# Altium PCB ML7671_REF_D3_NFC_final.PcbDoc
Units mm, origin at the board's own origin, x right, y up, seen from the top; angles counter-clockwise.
Board outline 64 x 8.2 mm, 4 copper layers (Top Layer, Inner Layer 1, Inner Layer 2, Bottom Layer), stack 0.195 mm thick; 63 components, 45 nets, 175 pads, 328 vias.
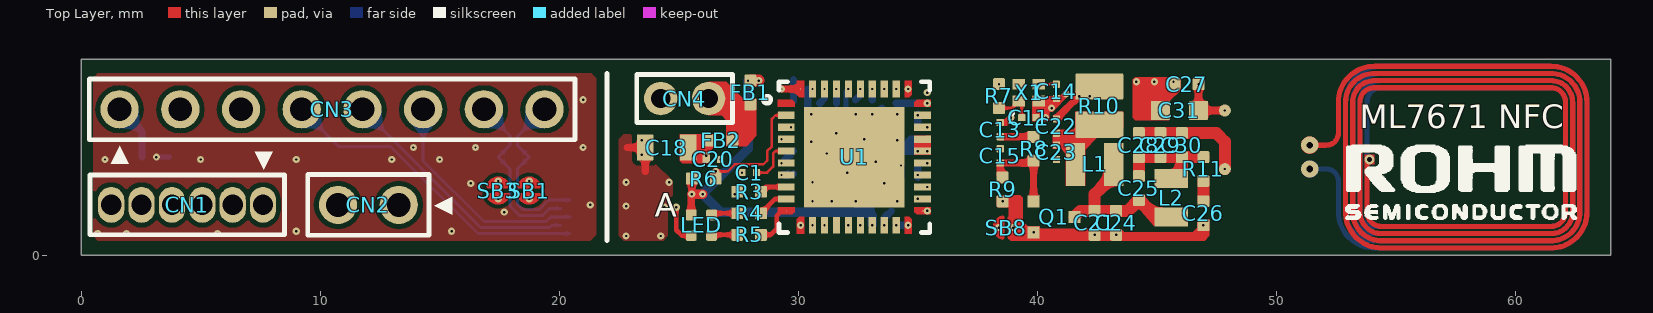
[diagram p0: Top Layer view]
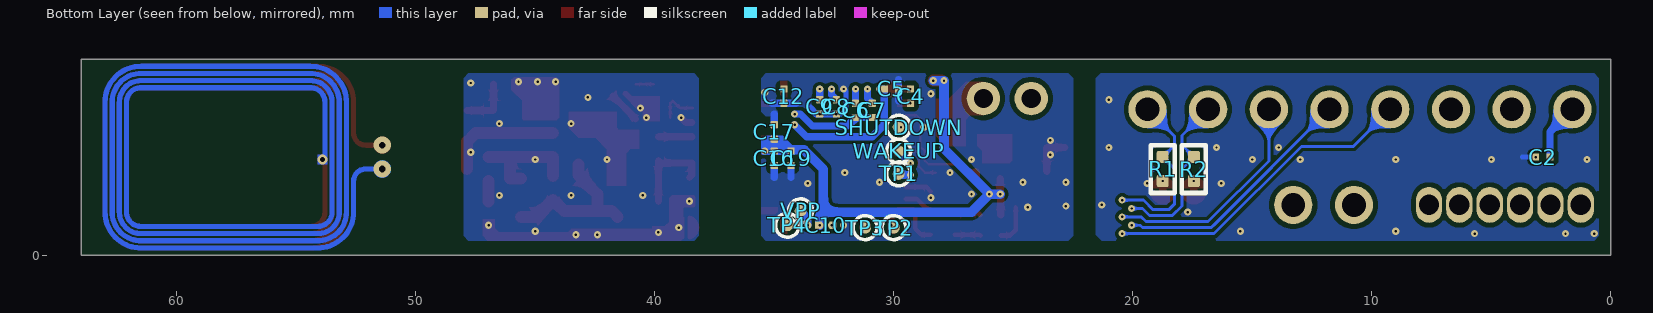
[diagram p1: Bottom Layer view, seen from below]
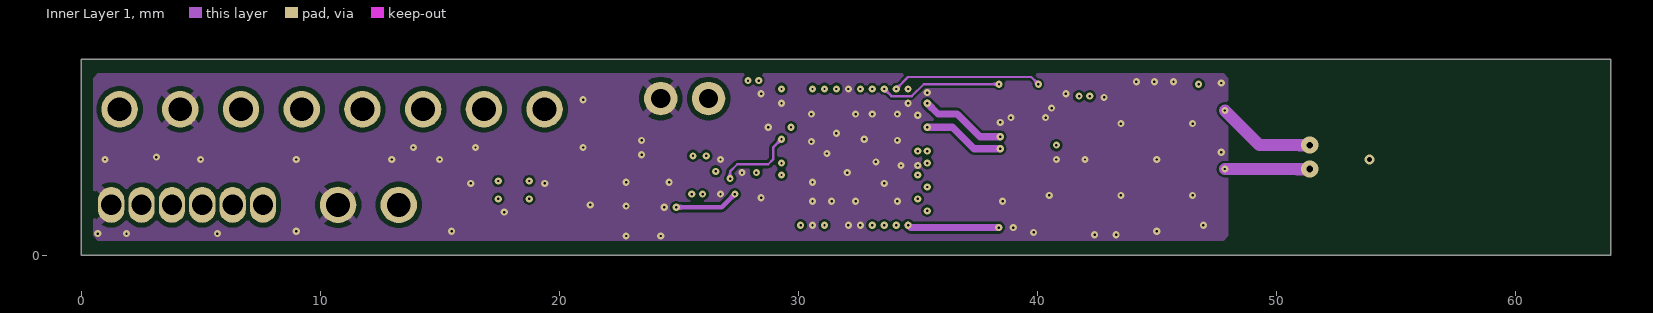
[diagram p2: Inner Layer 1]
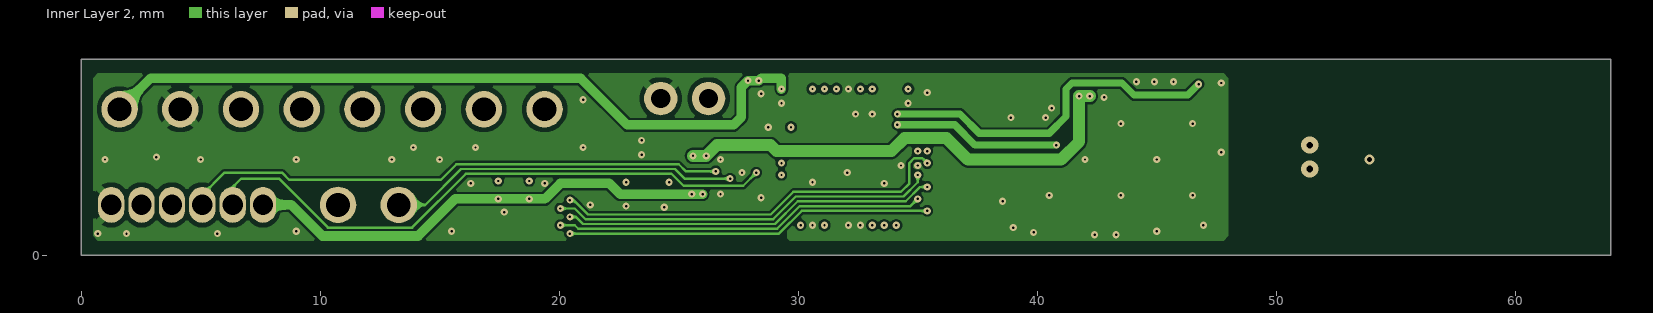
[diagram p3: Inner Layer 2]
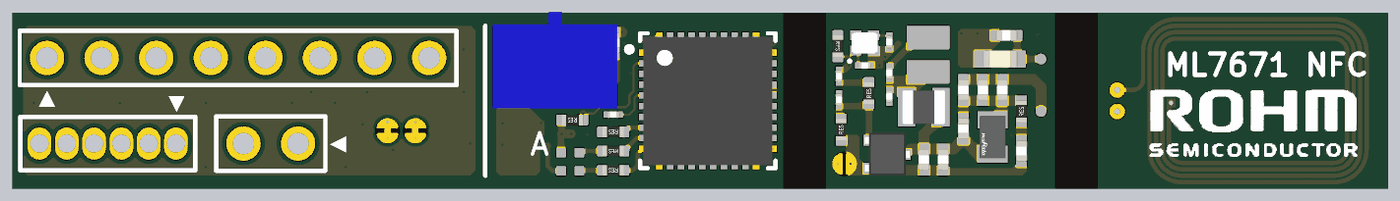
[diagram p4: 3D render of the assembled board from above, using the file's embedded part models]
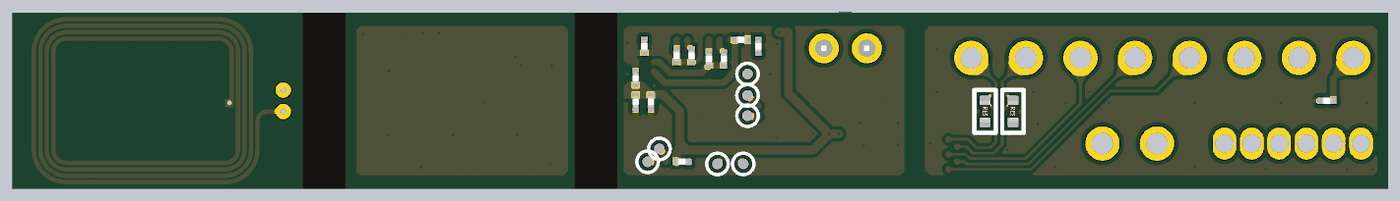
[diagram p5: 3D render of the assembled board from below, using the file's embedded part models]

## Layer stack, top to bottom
Top Solder: solder mask 0.02, Solder Resist, Dk 3.5
Top Layer: signal copper 0.035
Dielectric 1: prepreg 0.005, Composite dielectric, Dk 4.1
Dielectric 2: prepreg 0.025, Composite dielectric, Dk 4.1
Inner Layer 1: signal copper 0.02
Dielectric 3: core 0.025, R-1776KR, Dk 4.8
Inner Layer 2: signal copper 0.02
Dielectric 4: prepreg 0.025, Composite dielectric, Dk 4.1
Dielectric 5: prepreg 0.005, Composite dielectric, Dk 4.1
Bottom Layer: signal copper 0.035
Bottom Solder: solder mask 0.02, Solder Resist, Dk 3.5

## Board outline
0,0 0,8.2 64,8.2 64,0

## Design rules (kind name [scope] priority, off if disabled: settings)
BoardOutlineClearance [All] p1: gap=0.5 ignorepadtopadclearanceinfootprint=FALSE
Clearance Clearance_1 [IsKeepOut] p1: gap=0 ignorepadtopadclearanceinfootprint=TRUE
Clearance Clearance_l2 [OnLayer('Inner Layer 1')] p2: gap=0.1 ignorepadtopadclearanceinfootprint=TRUE except(0: Arc-Text Track-Text SMDPad-Text THPad-Text Via-Text Fill-Text Poly-Text Region-Text; 0.15: Arc-SMDPad Track-SMDPad SMDPad-Via THPad-Via; 0.2: Arc-THPad Arc-Hole Track-THPad Track-Hole SMDPad-SMDPad SMDPad-THPad SMDPad-Fill SMDPad-Poly SMDPad-Region SMDPad-Hole THPad-THPad THPad-Fill THPad-Poly THPad-Region THPad-Hole Via-Hole Fill-Hole Poly-Hole Region-Region Region-Hole; 0.3: Fill-Fill Fill-Poly Fill-Region)
Clearance Clearance_l3 [OnLayer('Inner Layer 2')] p3: gap=0.1 ignorepadtopadclearanceinfootprint=TRUE except(0: Arc-Text Track-Text SMDPad-Text THPad-Text Via-Text Fill-Text Poly-Text Region-Text; 0.15: Arc-SMDPad Track-SMDPad SMDPad-Via THPad-Via; 0.2: Arc-THPad Arc-Hole Track-THPad Track-Hole SMDPad-SMDPad SMDPad-THPad SMDPad-Fill SMDPad-Poly SMDPad-Region SMDPad-Hole THPad-THPad THPad-Fill THPad-Poly THPad-Region THPad-Hole Via-Hole Fill-Hole Poly-Hole Region-Region Region-Hole; 0.3: Fill-Fill Fill-Poly Fill-Region Poly-Poly)
Clearance Clearance_bottom [OnLayer('Bottom Layer')] p4: gap=0.2 ignorepadtopadclearanceinfootprint=TRUE except(0.1: Text-Text Text-Hole; 0.13: Arc-Arc Arc-Track Arc-Via Track-Track Track-Via; 0.15: Arc-SMDPad Arc-Fill Arc-Poly Arc-Region Track-SMDPad Track-Fill Track-Poly Track-Region SMDPad-Via THPad-Via Via-Via Via-Fill Via-Poly Via-Region Poly-Region; 0.3: Fill-Fill Fill-Poly Fill-Region Poly-Poly)
Clearance Clearance_top [OnLayer('Top Layer')] p5: gap=0.2 ignorepadtopadclearanceinfootprint=TRUE except(0.1: Text-Text Text-Hole; 0.13: Arc-Arc Arc-Track Arc-Via Track-Track Track-Via; 0.15: Arc-SMDPad Arc-Fill Arc-Poly Arc-Region Track-SMDPad Track-Fill Track-Poly Track-Region SMDPad-Via Via-Via Via-Fill Via-Poly Via-Region Poly-Region; 0.3: Fill-Fill Fill-Poly Fill-Region Poly-Poly)
HoleSize [All] p1: absolutevalues=TRUE maxlimit=4 minlimit=0.2 maxpercent=80.000 minpercent=20.000
MinimumSolderMaskSliver [All] p1: minsoldermaskwidth=0.15
PolygonConnect PolygonConnect_top [OnLayer('Top Layer')] p1: thpad.connectstyle=NoConnect thpad.reliefconductorwidth=0.3 thpad.reliefentries=4 thpad.polygonreliefangle="90 Angle" thpad.airgapwidth=0.2 smdpad.connectstyle=NoConnect smdpad.reliefconductorwidth=0.254 smdpad.reliefentries=4 smdpad.polygonreliefangle="90 Angle" smdpad.airgapwidth=0.2 via.connectstyle=Direct via.reliefconductorwidth=0.254 via.reliefentries=4 via.polygonreliefangle="90 Angle" via.airgapwidth=0.254
PolygonConnect PolygonConnect_bottom [OnLayer('Bottom Layer')] p2: thpad.connectstyle=NoConnect thpad.reliefconductorwidth=0.3 thpad.reliefentries=4 thpad.polygonreliefangle="90 Angle" thpad.airgapwidth=0.2 smdpad.connectstyle=NoConnect smdpad.reliefconductorwidth=0.254 smdpad.reliefentries=4 smdpad.polygonreliefangle="90 Angle" smdpad.airgapwidth=0.2 via.connectstyle=Direct via.reliefconductorwidth=0.254 via.reliefentries=4 via.polygonreliefangle="90 Angle" via.airgapwidth=0.254
PolygonConnect [All] p3: thpad.connectstyle=Relief thpad.reliefconductorwidth=0.3 thpad.reliefentries=4 thpad.polygonreliefangle="90 Angle" thpad.airgapwidth=0.2 thpad.conductorbypadedge=TRUE thpad.mindistance=0.381 thpad.enablemindistance=FALSE smdpad.connectstyle=NoConnect smdpad.reliefconductorwidth=0.254 smdpad.reliefentries=4 smdpad.polygonreliefangle="90 Angle" smdpad.airgapwidth=0.2 via.connectstyle=Direct via.reliefconductorwidth=0.254 via.reliefentries=4 via.polygonreliefangle="90 Angle" via.airgapwidth=0.254
RoutingVias [All] p1: holewidth=0.6 width=0.3 viastyle="Through Hole" minholewidth=0.5 minwidth=0.2 maxholewidth=1.4 maxwidth=1
SilkToSilkClearance [All] p1: silktosilkclearance=0.1
SilkToSolderMaskClearance [IsPad] p1: minsilkscreentomaskgap=0.1 clearancetoexposedcopper=TRUE
SolderMaskExpansion [All] p1: expansion=0.05 istentingtop=FALSE
SupplyNets "Schematic Supply Nets_6" [InNet('VDD_IO')] p1: voltage=0.000
SupplyNets "Schematic Supply Nets_2" [InNet('GND')] p2: voltage=0.000
Width [All] p1: maxlimit=3 minlimit=0.1 preferedwidth=0.12 midlayer1_prefwidth=0.1 midlayer2_prefwidth=0.1 minimp=50.000000 maximp=50.000000 favimp=50.000000
26 further rules are at their usual default settings.

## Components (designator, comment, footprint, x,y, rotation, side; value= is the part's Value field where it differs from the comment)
C1 "Cap" 0603-1_00 27.95,3.45 r180 top value=N.M.
C2 "Cap" 0603-1_00 2.85,4.1 r0 bottom value=0.1uF
C4 "Cap" 0603-1_00 29.3,6.65 r270 bottom value=2.2uF
C5 "Cap" 0603-1_00 30.1,6.95 r180 bottom value=N.M.
C6 "Cap" 0603-1_00 31.6,6.05 r270 bottom value=560pF
C7 "Cap" 0603-1_00 30.9,6.05 r270 bottom value=560pF
C8 "Cap" 0603-1_00 32.4,6.2 r90 bottom value=0.47uF
C9 "Cap" 0603-1_00 33.1,6.2 r90 bottom value=2.2uF
C10 "Cap" 0603-1_00 32.85,1.25 r180 bottom value=0.1uF
C11 "Cap" 0603-1_00 39.65,5.75 r180 top value=10pF
C12 "Cap" 0603-1_00 34.6,6.65 r270 bottom value=0.47uF
C13 "Cap" 0603-1_00 38.45,5.25 r90 top value=1nF
C14 "Cap" 0603-1_00 40.8,6.85 r90 top value=10pF
C15 "Cap" 0603-1_00 38.45,4.15 r270 top value=1nF
C16 "Cap" 0603-1_00 35,4.05 r270 bottom value=47pF
C17 "Cap" 0603-1_00 35,5.15 r90 bottom value=47pF
C18 "Cap" GCM21_2125_00 24.5,4.5 r180 top value=47uF
C19 "Cap" 0603-1_00 34.3,4.05 r270 bottom value=2.2uF
C20 "Cap" 0603-1_00 26.45,4 r0 top value=2.2uF
C21 "Cap" CC1005_02 42.4,1.35 r270 top value=120pF
C22 "Cap" 0603-1_00 40.8,5.4 r270 top value=100pF
C23 "Cap" 0603-1_00 40.8,4.3 r270 top value=100pF
C24 "Cap" CC1005_02 43.3,1.35 r270 top value=N.M.
C25 "N.M." CC1005_02 44.25,2.8 r90 top
C26 "N.M." CC1005_02 46.95,1.75 r270 top
C27 "Cap" CC1005_02 46.25,7.15 r0 top value=390pF
C28 "Cap" CC1005_02 44.25,4.6 r90 top value=120pF
C29 "Cap" CC1005_02 45.15,4.6 r90 top value=12pF
C30 "Cap" CC1005_02 46.05,4.6 r90 top value=N.M.
C31 "Cap" CC1608_00 45.95,6.05 r0 top value=2.2nF
CN1 "MHDR1X6" CN6_XB-1-5 7.61,2.1 r180 top value="6-Pin Header"
CN2 "Header 2" JP2-2.54_01 12.02,2.1 r180 top value="2-Pin Header"
CN3 "Header 8" JP8-2.54_01 10.5,6.1 r0 top value="8-Pin Header"
CN4 "Header 2" JP2-2.0_C0.8 25.25,6.55 r180 top locked value="2-Pin Header"
FB1 "BLM15AG" CC1005_02 28,6.8 r270 top value=-
FB2 "BLM15AG" CC1005_02 26.75,4.8 r0 top value=-
L1 "DFE2016CKA-1R0M" L_2_2016_t065 42.4,3.8 r180 top value=4.7uH
L2 "DFE21CCNR24MELL1" L_2_2012_t08 45.6,2.4 r270 top value=240nH
LED "SMLP34RGBN1W3" SMLP34RGB_00 25.95,1.25 r90 top value=-
Q1 "RSF014N03TL" MMP_3_2120_TUMT_GSD 40.7,1.6 r0 top value=-
R1 "2.2kΩ" RR1005_02 18.75,3.6 r270 bottom
R2 "2.2kΩ" RR1005_02 17.45,3.6 r270 bottom
R3 "1.8kΩ" RR1005_02 27.95,2.65 r180 top
R4 "1.8kΩ" RR1005_02 27.95,1.75 r180 top
R5 "1.8kΩ" RR1005_02 27.95,0.85 r180 top
R6 "2.2kΩ" RR1005_02 26.05,3.2 r180 top
R7 "0Ω" RR1005_02 38.4,6.65 r270 top
R8 "51Ω" RR1005_02 39.85,4.45 r90 top
R9 "510Ω" RR1005_02 38.55,2.75 r90 top
R10 "220mΩ" LTR10_00 42.6,6.25 r270 top
R11 "N.M." RR1005_02 46.95,3.6 r90 top
SB1 "Solderbridge Shorted" SOLDERBRIDGE_SHORTED_POWER 18.75,2.7 r90 top
SB3 "Solderbridge Shorted" SOLDERBRIDGE_SHORTED_POWER 17.45,2.7 r90 top
SB8 "Solderbridge" SOLDERBRIDGE 38.7,1.15 r180 top
SHUTDOWN "" TP_PAD0.5_01 29.8,5.35 r90 bottom value="Small Pad"
TP1 "" TP_PAD0.5_01 29.8,3.4 r180 bottom value="Small Pad"
TP2 "" TP_PAD0.5_01 30,1.15 r90 bottom value="Small Pad"
TP3 "" TP_PAD0.5_01 31.2,1.15 r90 bottom value="Small Pad"
TP4 "" TP_PAD0.5_01 34.45,1.25 r90 bottom value="Small Pad"
U1 "-" QFN50P600X600X80_41N_ROHM 32.35,4.1 r0 top
VPP "" TP_PAD0.5_01 33.9,1.85 r90 bottom value="Small Pad"
WAKEUP "" TP_PAD0.5_01 29.8,4.35 r90 bottom value="Small Pad"
X1 "CX1210SB27120B0FLKC2" X_4_1210_0.52x0.45 39.65,6.8 r0 top value=-

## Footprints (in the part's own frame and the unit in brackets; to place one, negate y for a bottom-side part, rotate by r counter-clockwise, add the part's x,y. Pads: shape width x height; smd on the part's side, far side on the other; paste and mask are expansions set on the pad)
0603-1_00 [mm]
  rrect17% 0.3x0.3 smd: 1(-0.3,0) 2(0.3,0)
  body extent -0.3,-0.16 0.3,0.16, height 0.32
CC1005_02 [mm]
  rrect22% 0.5x0.5 smd: 1(-0.5,0) 2(0.5,0)
  body extent -0.5,-0.26 0.5,0.26, height 0.52
CC1608_00 [mm]
  rrect12% 0.8x0.8 smd: 1(-0.8,0) 2(0.8,0)
  body extent -0.8,-0.41 0.8,0.41, height 0.82
CN6_XB-1-5 [mm] "XB-1-5-6P プリント板ニ段重ね用コンスルー"
  oval 1.1x1.5 hole 0.85 mask-2539.97: 1(0,0) 2(1.27,0) 3(2.54,0) 4(3.81,0) 5(5.08,0) 6(6.35,0)
  silkscreen extent -0.9,-1.25 7.24,1.25
GCM21_2125_00 [mm]
  rrect14% 0.7x1.1 smd: 1(-0.9,0) 2(0.9,0)
  body extent -1,-0.63 1,0.64, height 0.87
JP2-2.0_C0.8 [mm]
  round 1.4 hole 0.8: 1(-1,0) 2(1,0)
  silkscreen extent -2,-1 2,1, body extent -2.9,-1.7 2.9,2.8, height 8.13
JP2-2.54_01 [mm]
  round 1.6 / inner round 1.524 / far side round 1.6 hole 1: 1(-1.27,0) 2(1.27,0)
  silkscreen extent -2.54,-1.27 2.54,1.27
JP8-2.54_01 [mm]
  round 1.6 / inner round 1.524 / far side round 1.6 hole 1: 1(-8.89,0) 2(-6.35,0) 3(-3.81,0) 4(-1.27,0) 5(1.27,0) 6(3.81,0) 7(6.35,0) 8(8.89,0)
  silkscreen extent -10.16,-1.27 10.16,1.27
L_2_2012_t08 [mm] "default"
  rect 0.8x1.4 smd paste+0: 1(-0.8,0) 2(0.8,0)
  body extent -1,-0.6 1,0.6, height 0.8
L_2_2016_t065 [mm] "default"
  rect 0.8x1.8 smd paste+0: 1(-0.8,0) 2(0.8,0)
  body extent -1,-0.8 1,0.8, height 0.65
LTR10_00 [mm]
  rrect9% 1.1x2 smd: 1(-0.8,0) 2(0.8,0)
  body extent -0.6,-1 0.6,1, height 0.55
MMP_3_2120_TUMT_GSD [mm] "default"
  rect 0.5x0.5 smd paste+0 mask+0.05: D(0.85,0) G(-0.85,0.65) S(-0.85,-0.65)
  body extent -1.05,-1 1.05,1, height 0.85
QFN50P600X600X80_41N_ROHM [mm] "QFN, 40-Leads, Body 6.00x6.00mm, Pitch 0.50mm, Thermal Pad 4.20x4.20mm"
  round 0.025 smd mask+0: 1(-2.85,2.25) 10(-2.85,-2.25) 11(-2.25,-2.85) 20(2.25,-2.85) 21(2.85,-2.25) 30(2.85,2.25) 31(2.25,2.85) 40(-2.25,2.85)
  rect 0.7x0.3 smd mask+0.05: 2(-2.85,1.75) 3(-2.85,1.25) 4(-2.85,0.75) 5(-2.85,0.25) 6(-2.85,-0.25) 7(-2.85,-0.75) 8(-2.85,-1.25) 9(-2.85,-1.75) 22(2.85,-1.75) 23(2.85,-1.25) 24(2.85,-0.75) 25(2.85,-0.25) 26(2.85,0.25) 27(2.85,0.75) 28(2.85,1.25) 29(2.85,1.75)
  rect 0.3x0.7 smd mask+0.05: 12(-1.75,-2.85) 13(-1.25,-2.85) 14(-0.75,-2.85) 15(-0.25,-2.85) 16(0.25,-2.85) 17(0.75,-2.85) 18(1.25,-2.85) 19(1.75,-2.85) 32(1.75,2.85) 33(1.25,2.85) 34(0.75,2.85) 35(0.25,2.85) 36(-0.25,2.85) 37(-0.75,2.85) 38(-1.25,2.85) 39(-1.75,2.85)
  rect 4.2x4.2 smd mask+0.05: 41(0,0)
  Top Layer region: -2.5,-2.3 -2.6,-2.4 -3.2,-2.4 -3.2,-2.1 -2.5,-2.1
  Top Layer region: 2.3,2.5 2.4,2.6 2.4,3.2 2.1,3.2 2.1,2.5
  Top Layer region: 2.5,2.3 2.6,2.4 3.2,2.4 3.2,2.1 2.5,2.1
  Top Layer region: 2.5,-2.3 2.6,-2.4 3.2,-2.4 3.2,-2.1 2.5,-2.1
  Top Layer region: 2.3,-2.5 2.4,-2.6 2.4,-3.2 2.1,-3.2 2.1,-2.5
  Top Layer region: -2.3,-2.5 -2.4,-2.6 -2.4,-3.2 -2.1,-3.2 -2.1,-2.5
  Top Layer region: -2.3,2.5 -2.4,2.6 -2.4,3.2 -2.1,3.2 -2.1,2.5
  Top Layer region: -2.5,2.3 -2.6,2.4 -3.2,2.4 -3.2,2.1 -2.5,2.1
  silkscreen extent -3.77,-3.15 3.15,3.15, body extent -3,-3 3,3, height 0.8
RR1005_02 [mil]
  rrect22% 19.68x19.68 smd: 1(-19.69,0) 2(19.69,0)
  silkscreen extent -39,-20 39,20, body extent -20,-10 20,10, height 14
SMLP34RGB_00 [mm]
  rrect22% 0.45x0.45 smd: 1(0.425,0.425) 2(0.425,-0.425) 3(-0.425,-0.425) 4(-0.425,0.425)
  body extent -0.5,-0.5 0.5,0.5, height 0.2
SOLDERBRIDGE [mm]
  round 0.2 smd paste-10: 1(-0.312,0) 2(0.312,0)
  Top Layer region: -0.077,-0.432 -0.152,-0.505 -0.271,-0.467 -0.335,-0.424 -0.409,-0.351 -0.462,-0.292 -0.521,-0.193 -0.549,-0.099 -0.544,0.122 -0.518,0.193 -0.434,0.33 -0.351,0.411 -0.259,0.469 -0.157,0.5 -0.107,0.483 -0.077,0.43
  Top Layer region: 0.077,0.432 0.152,0.505 0.271,0.467 0.335,0.424 0.409,0.351 0.462,0.292 0.521,0.193 0.549,0.099 0.544,-0.122 0.518,-0.193 0.434,-0.33 0.351,-0.411 0.259,-0.469 0.157,-0.5 0.107,-0.483 0.077,-0.43
  Top Layer lines w0.152: 0.153,0.431 cw(c0.042,0) 0.153,-0.431 ; -0.153,0.431 ccw(c-0.042,0) -0.153,-0.431
SOLDERBRIDGE_SHORTED_POWER [mm]
  round 0.2 smd paste-10: 1(-0.338,0) 2(0.338,0)
  Top Layer region: 0.102,0.432 0.178,0.505 0.296,0.467 0.361,0.424 0.434,0.351 0.488,0.292 0.546,0.193 0.574,0.099 0.569,-0.122 0.544,-0.193 0.46,-0.33 0.376,-0.411 0.284,-0.469 0.183,-0.5 0.132,-0.483 0.102,-0.43
  Top Layer region: -0.102,-0.432 -0.178,-0.505 -0.296,-0.467 -0.361,-0.424 -0.434,-0.351 -0.488,-0.292 -0.546,-0.193 -0.574,-0.099 -0.569,0.122 -0.544,0.193 -0.46,0.33 -0.376,0.411 -0.284,0.469 -0.183,0.5 -0.132,0.483 -0.102,0.43
  Top Layer lines w0.152: -0.178,0.431 ccw(c-0.068,0) -0.178,-0.431 ; 0.178,0.431 cw(c0.068,0) 0.178,-0.431
  Top Layer lines w0.3: -0.338,0 0.338,0
TP_PAD0.5_01 [mm]
  round 0.5 smd: 1(0,0)
  silkscreen extent -0.5,-0.5 0.5,0.5
X_4_1210_0.52x0.45 [mm] "KYOCERA"
  rect 0.52x0.45 smd: 1(-0.415,-0.35) 2(0.415,-0.35) 3(0.415,0.35) 4(-0.415,0.35)
  silkscreen extent -0.75,-0.9 -0.65,-0.8, body extent -0.6,-0.5 0.6,0.5, height 0.3

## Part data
C1 C5 C24 C30: "Capacitor", Part Number=-
C2 C10: "Capacitor", Part Number=GRM033R61C104KE18#
C4 C9 C19 C20: "Capacitor", Part Number=GRM035R61C225ME01#
C6 C7: "Capacitor", Part Number=GRM033R71C561KA01#
C8 C12: "Capacitor", Part Number=GRM033R60J474KE90#
C11 C14: "Capacitor", Part Number=GRM0335C1H100FA01#
C13: "Capacitor", Part Number=GRM033B11E102KA01#
C15: "Capacitor", Part Number=GRM0335C1E102FA01#
C16 C17: "Capacitor", Part Number=GRM0335C1H470FA01#
C18: "Capacitor", Part Number=GRM21BR61A476ME15#
C21: "Capacitor", Part Number=GCM1555C1H121FA16#
C22 C23: "Capacitor", Part Number=GRM0335C1H101FA01#
C25 C26: library part Cap, "Capacitor", Part Number=-
C27: "Capacitor", Part Number=GRM1555C1H391FA01#
C28: "Capacitor", Part Number=GRM1555C2A121GE01#
C29: "Capacitor", Part Number=GQM1555C2D120FB01D
C31: "Capacitor", Part Number=GCM1885C1H222GA16#
CN1: "Header, 6-Pin", Part Number=XB-1-5-6P
CN2: "Header, 2-Pin", Part Number=PH-1x2SG
CN3: "Header, 8-Pin", Part Number=PH-1x8SG
CN4: "Header, 2-Pin", Part Number=PH2-1X2SBG
FB1 FB2: library part Inductor, "Inductor", Part Number=BLM15AG100SN1D
L1: library part Inductor, "Inductor", Part Number=DFE2016CTC-4R7M
L2: library part Inductor, "Inductor", Part Number=LQM2MPNR24MEHL
LED: library part RGB_LED, "RGB LED"
Q1: library part MOSFET-N, "N-Channel MOSFET", Part Number=RQ5E035BN
R1 R2 R6: library part Res3, "Resistor", Part Number=MCR01MZPJ222
R3 R4 R5: library part Res3, "Resistor", Part Number=MCR01MZPJ182
R7: library part Res3, "Resistor", Part Number=PMR01HZPJ000
R8: library part Res3, "Resistor", Part Number=MCR01MZPJ510
R9: library part Res3, "Resistor", Part Number=MCR01MZPJ511
R10: library part Res3, "Resistor", Part Number=LTR10LEZPFLR220
R11: library part Res3, "Resistor", Part Number=-
SB1 SB3: library part SOLDERBRIDGE_SHORTED, "Shorted Solderbridge"
SB8: library part SOLDERBRIDGE
SHUTDOWN TP1 TP2 TP3 TP4 VPP WAKEUP: library part TP, "TP", Part Number=-
U1: library part ML7663, "NFC TX, WQFN40", Part Number=ML7671
X1: library part SMD_Crystal, "SMD Crystal"

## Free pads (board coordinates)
  round 0.5 smd: 1(47.85,6.05) 1(47.85,3.6)

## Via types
v1: diameter 0.3, hole 0.1, Top Layer to Inner Layer 1, tented both sides, 120 vias
v2: diameter 0.3, hole 0.1, Inner Layer 1 to Inner Layer 2, tented both sides, 107 vias
v3: diameter 0.3, hole 0.1, Inner Layer 2 to Bottom Layer, tented both sides, 98 vias
v4: diameter 0.72, hole 0.28, Top Layer to Bottom Layer, 2 vias
v5: diameter 0.4, hole 0.2, Top Layer to Bottom Layer, 1 vias

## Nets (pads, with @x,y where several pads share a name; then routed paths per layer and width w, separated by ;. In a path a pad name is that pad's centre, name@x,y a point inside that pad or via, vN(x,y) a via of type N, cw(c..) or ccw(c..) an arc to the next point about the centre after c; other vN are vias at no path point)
AIN2: C5.1 C22.2 C23.1 L1.2 R10.2 U1.39 | length 12.9
  Inner Layer 2 w0.3: v3(34.15,5.45) 36.55,5.45 37.4,4.6 v2(40.8,4.6)
  Bottom Layer w0.3: v3(30.6,6.95) C5.1 30.4,5.45 30.9,4.95 33.65,4.95 v3(34.15,5.45)
  other v1: 40.8,4.6 30.6,6.95
  other v2: 30.6,6.95
GND: C1.2 C2.2 C4.2 C5.2 C8.1 C9.1 C10.2 C11.1 C12.2 C13.2 C14.1 C16.2 C17.2 C18.2 C19.2 C20.2 C21.2 C23.2 C24.2 C26.2 C27.1 C31.1 CN1.6 CN2.2 CN3.2 CN4.2 Q1.S R9.1 SB8.1 U1.12 U1.15 U1.16 U1.29 U1.36 U1.41 X1.2 | length 8.8
  Top Layer w0.3: 22.85,4.5 C18.2 23.6,3.5 ; v1(38.45,5.55) 38.7,5.55 v1(38.9,5.75)
  Inner Layer 1 w0.1: v1@32,3.4 v3(32.05,3.45)
  Bottom Layer w0.2: v3(3.15,4.1) 3.7,4.1 ; v3(32.1,6.95) 32,6.85 32,6.1 32.2,5.9 v3(32.4,5.9)
  Bottom Layer w0.3: 29.8,6.45 C5.2 29.8,7.35 ; v3(32.4,5.9) v3(33.1,5.9) 33.25,5.9 33.5,6.15 ; 34.1,6.35 v2(34.6,6.35) 34.75,6.35 35.1,6.35 ; 34.3,3.25 v1(34.3,3.75) ; 35,3.25 v3(35,3.75) ; C17.2 35,5.9
  other v1: 22.8,0.8 24.25,0.8 42.4,0.85 43.3,0.85 0.7,0.9 1.9,0.9 5.7,0.9 39.85,0.95 9,1 15.5,1 39,1.15 30.6,1.25 32.1,1.25 32.6,1.25 46.95,1.25 17.7,1.8 24.4,2 22.8,2.05 21.3,2.1 30.6,2.25 31.4,2.25 32.4,2.25 34.15,2.25 38.55,2.25 16.3,3 33.6,3 22.8,3.05 24.6,3.05 30.6,3.05 27.65,3.45 32.05,3.45 33.25,3.9 1,4 5,4 9,4 13,4 15,4 26.75,4 40.8,4 3.15,4.1 23.45,4.2 31.2,4.25 13.9,4.5 16.5,4.5 21,4.5 30.55,4.75 23.45,4.8 34.15,4.8 32.765,4.85 31.6,5.1 40.35,5.75 35,5.85 30.55,5.9 32.4,5.9 33.1,5.9 34.15,5.9 40.6,6.15 21,6.5 41.2,6.75 35.4,6.8 32.1,6.95 44.15,7.25 44.9,7.25 45.7,7.25
  other v2: 42.4,0.85 43.3,0.85 0.7,0.9 1.9,0.9 5.7,0.9 39.85,0.95 9,1 15.5,1 45,1 39,1.15 30.6,1.25 32.1,1.25 32.6,1.25 46.95,1.25 17.7,1.8 24.4,2 22.8,2.05 21.3,2.1 38.55,2.25 28.45,2.4 40.5,2.5 43.5,2.5 46.5,2.5 26.75,2.55 16.3,3 19.4,3 33.6,3 22.8,3.05 24.6,3.05 30.6,3.05 27.65,3.45 32.05,3.45 34.3,3.75 35,3.75 1,4 5,4 9,4 13,4 15,4 26.75,4 42,4 45,4 3.15,4.1 23.45,4.2 47.7,4.3 13.9,4.5 16.5,4.5 21,4.5 23.45,4.8 28.75,5.35 43.5,5.5 46.5,5.5 38.9,5.75 40.35,5.75 32.4,5.9 33.1,5.9 40.6,6.15 29.3,6.35 21,6.5 42.8,6.6 28.45,6.75 35.4,6.8 32.1,6.95 47.7,7.2 44.15,7.25 44.9,7.25 45.7,7.25
  other v3: 42.4,0.85 43.3,0.85 0.7,0.9 1.9,0.9 5.7,0.9 39.85,0.95 9,1 15.5,1 45,1 39,1.15 30.6,1.25 32.1,1.25 32.6,1.25 46.95,1.25 17.7,1.8 24.4,2 22.8,2.05 21.3,2.1 38.55,2.25 28.45,2.4 40.5,2.5 43.5,2.5 46.5,2.5 26.75,2.55 16.3,3 19.4,3 33.6,3 22.8,3.05 24.6,3.05 30.6,3.05 27.65,3.45 34.3,3.75 1,4 5,4 9,4 13,4 15,4 26.75,4 42,4 45,4 23.45,4.2 47.7,4.3 13.9,4.5 16.5,4.5 21,4.5 23.45,4.8 28.75,5.35 43.5,5.5 46.5,5.5 38.9,5.75 40.35,5.75 40.6,6.15 29.3,6.35 34.6,6.35 21,6.5 42.8,6.6 28.45,6.75 35.4,6.8 47.7,7.2 44.15,7.25 44.9,7.25 45.7,7.25
INT_S: CN3.6 U1.23 | length 25.2
  Inner Layer 2 w0.1: v3(20.45,1.6) 20.7,1.6 21,1.3 29.033,1.3 29.983,2.25 34.5,2.25 35.1,2.85 v1(35.4,2.85)
  Bottom Layer w0.12: CN3.6 14.31,3.94 16.85,1.4 19.45,1.4 19.65,1.6 v3(20.45,1.6)
  other v2: 35.4,2.85
NetC6_1: C6.1 U1.37 | length 0.6
  Bottom Layer w0.3: C6.1 v3(31.6,6.95)
  other v1: 31.6,6.95
  other v2: 31.6,6.95
NetC6_2: C6.2 C7.2 C27.2 C31.2 pad.1@47.85,6.05 | length 24.8
  Top Layer w0.3: v1(46.75,7.15) C31.2 v1(47.85,6.05)
  Inner Layer 1 w0.5: v1(47.85,6.05) 49.3,4.6 51.4,4.6
  Inner Layer 2 w0.3: v3(34.15,5.9) 36.775,5.9 37.575,5.1 40.5,5.1 41.2,5.8 41.2,6.95 41.45,7.2 43.55,7.2 44.05,6.7 46.3,6.7 v1(46.75,7.15)
  Bottom Layer w0.3: C7.2 C6.2 31.95,5.4 33.4,5.4 33.9,5.9 v3(34.15,5.9)
  other v2: 46.75,7.15
NetC7_1: C7.1 U1.38 | length 0.7
  Bottom Layer w0.3: C7.1 31.1,6.55 v1(31.1,6.95)
  other v2: 31.1,6.95
  other v3: 31.1,6.95
NetC8_2: C8.2 U1.35 | length 0.5
  Bottom Layer w0.3: C8.2 32.6,6.7 v1(32.6,6.95)
  other v2: 32.6,6.95
  other v3: 32.6,6.95
NetC9_2: C9.2 U1.34 | length 0.4
  Bottom Layer w0.3: C9.2 v3(33.1,6.95)
  other v1: 33.1,6.95
  other v2: 33.1,6.95
NetC11_2: C11.2 R7.2 X1.1 | length 1.7
  Top Layer w0.12: R7.2 38.95,6.15 39.25,6.45 39.35,6.35 C11.2
NetC12_1: C12.1 U1.31
  other v1: 34.6,6.95
  other v2: 34.6,6.95
  other v3: 34.6,6.95
NetC13_1: C13.1 R8.2 U1.30 | length 5
  Top Layer w0.3: v1(38.45,4.95) R8.2
  Inner Layer 1 w0.3: v1(35.4,6.35) 35.85,5.9 36.65,5.9 37.6,4.95 v1(38.45,4.95)
NetC14_2: C14.2 U1.32 X1.3 | length 7
  Top Layer w0.1: v1(40.05,7.15) C14.2
  Inner Layer 1 w0.1: v1(34.1,6.95) 34.6,7.45 39.75,7.45 v1(40.05,7.15)
NetC15_1: C15.1 U1.28 | length 3.4
  Inner Layer 1 w0.3: v1(35.4,5.35) 36.45,5.35 37.35,4.45 v1(38.45,4.45)
NetC15_2: C15.2 Q1.G R8.1 R9.2 | length 3.8
  Top Layer w0.3: R9.2 38.45,3.35 C15.2 39.75,3.85 R8.1 Q1.G
NetC18_1: C18.1 C20.1 C22.1 FB2.1 R10.1 | length 21
  Top Layer w0.3: C22.1 v2(41.75,6.65)
  Inner Layer 2 w0.5: v2(25.6,4.15) v2(26.15,4.15) 26.6,4.6 28.85,4.6 29.1,4.35 33.9,4.35 34.45,4.9 36.2,4.9 37.1,4 41,4 41.75,4.75 v2(41.75,6.65) v1(42.2,6.65)
  other v1: 25.6,4.15 26.15,4.15 41.75,6.65
  other v2: 42.2,6.65
NetC21_1: C21.1 C24.1 C25.1 L1.1 L2.2 Q1.D | length 6.9
  Top Layer w0.5: Q1.D 41.8,1.85 C21.1 ; L1.1 43.2,3.35 42.4,2.55 C21.1 ; L2.2 44.95,1.6 C25.1 43.8,1.85 C24.1 C21.1
NetC25_2: C25.2 C28.1 C29.1 C30.1 L2.1 R11.2 | length 4.9
  Top Layer w0.5: C25.2 C28.1 C29.1 C30.1 ; L2.1 46.05,3.2 C30.1 ; R11.2 C30.1
NetC26_1: C26.1 R11.1 | length 0.9
  Top Layer w0.5: C26.1 R11.1
NetC28_2: C28.2 C29.2 C30.2 pad.1@47.85,3.6 | length 8.2
  Top Layer w0.5: C28.2 C29.2 C30.2 47.5,5.1 47.85,4.75 v1(47.85,3.6)
  Inner Layer 1 w0.5: v1(47.85,3.6) v4@51.122,3.6
  other v4: 51.4,3.6 51.4,4.6
  other v5: 53.9,4
NetCN4_1: CN4.1 FB1.2 FB2.2
NetLED_2: LED.2 R4.2 | length 1.1
  Top Layer w0.2: LED.2 26.45,1.75 R4.2
NetLED_3: LED.3 R5.2 | length 1.1
  Top Layer w0.2: LED.3 26.4,0.85 R5.2
NetLED_4: LED.4 R3.2 | length 4.3
  Top Layer w0.2: v1(24.9,2) 24.9,1.05 25.125,0.825 LED.4
  Inner Layer 1 w0.2: v1(24.9,2) 26.8,2 v1(27.35,2.55)
NetR1_2: R1.2 SB1.2
  other v1: 18.75,3.1
  other v2: 18.75,3.1
  other v3: 18.75,3.1
NetR2_2: R2.2 SB3.2
  other v1: 17.45,3.1
  other v2: 17.45,3.1
  other v3: 17.45,3.1
NetR3_1: R3.1 U1.8 | length 1.1
  Top Layer w0.2: R3.1 28.65,2.85 U1.8
NetR4_1: R4.1 U1.9 | length 1.3
  Top Layer w0.2: R4.1 29.05,2.35 U1.9
NetR5_1: R5.1 U1.10 | length 1.8
  Top Layer w0.2: R5.1 28.85,0.85 29.1,1.1 29.1,1.65 29.3,1.85 U1.10
NetR7_1: R7.1 U1.33 | length 5.1
  Inner Layer 1 w0.1: v1(33.6,6.95) 33.9,6.65 34.75,6.65 35.25,7.15 v1(38.4,7.15)
NetSB8_2: SB8.2 U1.20 | length 3.8
  Inner Layer 1 w0.3: v1(34.6,1.25) 34.7,1.15 v1(38.388,1.15)
NetSHUTDOWN_1: SHUTDOWN.1 U1.3
  other v1: 29.7,5.35
  other v2: 29.7,5.35
  other v3: 29.7,5.35
NetTP1_1: TP1.1 U1.7 | length 0.5
  Bottom Layer w0.3: v3(29.3,3.35) 29.75,3.35 TP1.1
  other v1: 29.3,3.35
  other v2: 29.3,3.35
NetTP2_1: TP2.1 U1.11
  other v1: 30.1,1.25
  other v2: 30.1,1.25
  other v3: 30.1,1.25
NetTP3_1: TP3.1 U1.13
  other v1: 31.1,1.25
  other v2: 31.1,1.25
  other v3: 31.1,1.25
NetTP4_1: TP4.1 U1.19 | length 0.4
  Bottom Layer w0.3: v1(34.1,1.25) TP4.1
  other v2: 34.1,1.25
  other v3: 34.1,1.25
NetU1_6: U1.6 WAKEUP.1 | length 0.7
  Bottom Layer w0.3: v1(29.3,3.85) WAKEUP.1
  other v2: 29.3,3.85
  other v3: 29.3,3.85
NetU1_18: U1.18 VPP.1 | length 0.7
  Bottom Layer w0.3: v1(33.6,1.25) 33.6,1.55 VPP.1
  other v2: 33.6,1.25
  other v3: 33.6,1.25
RESET_N: C1.1 CN1.2 U1.5 | length 26.9
  Top Layer w0.1: v1(28.25,3.45) 28.7,3.45 28.95,3.7 28.95,4.238 ; 28.95,4.25 29.05,4.35 U1.5
  Inner Layer 2 w0.1: CN1.2 6.34,2.84 6.7,3.2 8.275,3.2 10.325,1.15 13.85,1.15 16.1,3.4 24.7,3.4 25.2,2.9 27.7,2.9 v1(28.25,3.45)
  other v2: 28.25,3.45
SCL_S/SCLK_S: CN3.7 R2.1 U1.24 | length 23.4
  Inner Layer 2 w0.1: v3(20.05,1.95) 20.65,1.95 21.1,1.5 28.95,1.5 29.9,2.45 34.4,2.45 35,3.05 v1(35,3.35)
  Bottom Layer w0.12: CN3.7 17.95,5 17.95,4.6 R2.1 17.95,3.6 17.95,2.05 18.35,1.65 19.3,1.65 19.6,1.95 v3(20.05,1.95)
  other v2: 35,3.35
SCS_S: CN3.4 U1.21 | length 28.7
  Inner Layer 2 w0.1: v3(20.45,0.9) 29.199,0.9 30.149,1.85 v1(35.4,1.85)
  Bottom Layer w0.12: CN3.4 10.78,4.55 12.95,4.55 16.6,0.9 v3(20.45,0.9)
  other v2: 35.4,1.85
SDA_S/SDI_S: CN3.8 R1.1 U1.25 | length 24.1
  Inner Layer 2 w0.1: v3(20.45,2.3) 20.6,2.3 21.2,1.7 28.85,1.7 29.8,2.65 34.3,2.65 34.65,3 34.65,3.85 34.85,4.05 35.2,4.05 v1(35.4,3.85)
  Bottom Layer w0.12: CN3.8 18.25,4.96 18.25,4.6 R1.1 18.25,3.6 18.25,2.15 18.5,1.9 19.15,1.9 19.55,2.3 v3(20.45,2.3)
  other v2: 35.4,3.85
SDO_S: CN3.5 U1.22 | length 25.9
  Inner Layer 2 w0.1: v3(20.05,1.25) 20.65,1.25 20.8,1.1 29.116,1.1 30.066,2.05 34.7,2.05 v1(35,2.35)
  Bottom Layer w0.12: CN3.5 16.577,1.293 16.72,1.15 19.6,1.15 19.7,1.25 v3(20.05,1.25)
  other v2: 35,2.35
TEST0: CN1.3 R6.1 U1.2 | length 27.9
  Top Layer w0.1: v2(26.55,3.5) 27.05,3.5 27.35,3.8 28.55,3.8 28.7,3.95 28.7,4.35 28.9,4.55 28.9,5.7 29.05,5.85 U1.2
  Top Layer w0.3: R6.1 v2(26.55,3.5)
  Inner Layer 2 w0.1: CN1.3 5.07,2.52 6,3.45 8.4,3.45 8.7,3.15 15.05,3.15 15.7,3.8 25,3.8 25.3,3.5 v2(26.55,3.5)
  other v1: 26.55,3.5
TXD: CN2.1 U1.4 | length 17.9
  Inner Layer 1 w0.1: v2(27.15,3.2) 27.15,3.5 27.45,3.8 28.75,3.8 28.95,4 28.95,4.5 v1(29.3,4.85)
  Inner Layer 2 w0.1: CN2.1 14.4,2.1 15.9,3.6 24.85,3.6 25.25,3.2 v2(27.15,3.2)
VDD_IO: C2.1 C4.1 C10.1 C16.1 C17.1 C19.1 CN1.1 CN3.1 FB1.1 LED.1 R6.2 SB1.1 SB3.1 U1.17 U1.26 U1.27 U1.40 | length 74.7
  Top Layer w0.3: LED.1 25.525,2.525 v3(25.55,2.55) R6.2 ; v1(29.3,6.95) U1.40
  Top Layer w0.4: v3(25.55,2.55) v3(26,2.55)
  Top Layer w0.5: FB1.1 v2(28.35,7.3)
  Inner Layer 2 w0.4: CN3.1 2.91,7.4 20.9,7.4 22.85,5.45 27.3,5.45 27.625,5.775 27.625,7.025 v2(27.9,7.3) v2(28.35,7.3) 28.45,7.4 29.3,7.4 v1(29.3,6.95) ; CN1.1 8.8,2.1 10.1,0.8 14.1,0.8 15.65,2.35 v2(17.45,2.35) v2(18.75,2.35) 19.4,2.35 20.05,3 22.1,3 22.55,2.55 v3(25.55,2.55) v3(26,2.55)
  Bottom Layer w0.3: CN3.1 2.55,5.16 C2.1
  Bottom Layer w0.4: v3(25.55,2.55) v3(26,2.55) ; v2(28.35,7.3) v2(27.9,7.3) 27.9,4.45 v3(26,2.55) ; v3(33.1,1.25) 33.1,1.65 32.95,1.8 ; 34.65,4.4 33.75,4.4 32.95,3.6 32.95,1.8 ; v3(26,2.55) 26.75,1.8 32.95,1.8
  other v1: 33.1,1.25 17.45,2.35 18.75,2.35 25.55,2.55 26,2.55 35,4.35 35.4,4.35 27.9,7.3 28.35,7.3
  other v2: 33.1,1.25 25.55,2.55 26,2.55 35,4.35 35.4,4.35 29.3,6.95
  other v3: 35,4.35 35.4,4.35 29.3,6.95 27.9,7.3 28.35,7.3
pads on no net: CN1.4 CN1.5 CN3.3 U1.1 U1.14 X1.4

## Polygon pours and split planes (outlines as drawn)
GND on Bottom Layer "GND_L01_P-001" (solid, pour order 5): 0.5,0.8 0.7,0.6 21.3,0.6 21.55,0.85 21.55,7.4 21.35,7.6 0.7,7.6 0.5,7.4
GND on Bottom Layer "GND_L01_P-001" (solid, pour order 3): 22.5,0.8 22.7,0.6 35.35,0.6 35.55,0.8 35.55,7.4 35.35,7.6 22.7,7.6 22.5,7.4
GND on Bottom Layer "GND_L01_P-001" (solid, pour order 2): 38.15,0.8 38.35,0.6 47.8,0.6 48,0.8 48,7.4 47.8,7.6 38.35,7.6 38.15,7.4
GND on Top Layer "GND_L01_P-001" (solid, pour order 6): 0.5,0.8 0.7,0.6 21.3,0.6 21.55,0.85 21.55,7.4 21.35,7.6 0.7,7.6 0.5,7.4
GND on Top Layer "GND_L01_P-001" (solid, pour order 4): 22.5,4.85 22.7,5.05 23.95,5.05 23.95,3.9 24.75,3.1 24.75,2.5 24.55,2.3 24.55,0.8 24.35,0.6 22.7,0.6 22.5,0.8
GND on Inner Layer 1 "GND_L01_P-001" (solid, pour order 7): 0.7,7.6 0.5,7.4 0.5,0.8 0.7,0.6 47.8,0.6 48,0.8 48,7.4 47.8,7.6
GND on Inner Layer 2 "GND_L01_P-001" (solid, pour order 1): 0.7,7.6 0.5,7.4 0.5,0.8 0.7,0.6 47.8,0.6 48,0.8 48,7.4 47.8,7.6

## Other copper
Top Layer:
  region net GND: 38.35,2 38.3,2.05 38.3,2.45 38.35,2.5 39.3,2.5 39.4,2.4 39.4,1.4 39.6,1.2 40.1,1.2 40.1,1.15 40.15,1.1 43.5,1.1 43.65,0.95 46.5,0.95 46.7,1.15 46.7,1.5 47.2,1.5 47.2,0.8 47,0.6 38.9,0.6 38.8,0.7 38.8,1.95 38.75,2
  region net GND: 44,7.35 44.1,7.45 45.9,7.45 46,7.35 46,6.9 45.55,6.45 45.55,5.7 45.5,5.65 44.1,5.65 44,5.75
  region net GND: 39.8,6.65 40.95,6.65 41.15,6.85 41.3,6.85 41.35,6.8 41.35,6.7 40.65,6 40.55,6 40.5,5.95 40.5,5.65 40.45,5.6 39.8,5.6
  region net NetC28_2: 722 vertices and 0 holes, not listed, extent 51.039,0.2 63.1,8
  region net NetC18_1: 25.05,3.95 25.15,3.85 26.3,3.85 26.3,4.35 26.5,4.55 26.5,5.05 25.05,5.05
  region net NetCN4_1: 26.8,5.85 27,5.65 27,4.55 27.85,4.55 28.25,5 28.25,6.55 27.7,6.55 27,7.25 26.25,7.25 26,7 26,6.1 26.25,5.85
  region net AIN2: 40.65,5.25 40.65,4.45 41,4.45 41.2,4.25 41.2,2.9 42,2.9 42,4.4 42.5,4.9 43.2,4.9 43.6,5.3 43.6,6 41.6,6 41.6,5.35 41.5,5.25
  region net VDD_IO: 34.85,4.2 34.85,5 35.55,5 35.55,4.2
Inner Layer 2:
  pour cut-out: 29.7,0.55 29.55,0.7 29.55,1.15 29.313,0.913 29.313,0.563 29.3,0.55
Bottom Layer:
  pour cut-out: 35.15,5.8 35.35,5.8 35.55,6 35.55,5.25 35.15,5.25
  pour cut-out: 34.85,6.1 34.35,6.1 34.35,5.25 34.85,5.25
  region net NetC28_2: 724 vertices and 0 holes, not listed, extent 51.039,0.2 63.1,8
  region net VDD_IO: 34.15,4.5 34.65,5 35.35,5 35.55,4.8 35.55,4.25 35.5,4.2 34.15,4.2

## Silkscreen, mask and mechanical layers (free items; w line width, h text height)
Top Overlay:
  drawing of 21 lines, arcs and shapes, not listed
  text "ML7671 NFC" at 53.5,5.3 h1
Top Solder:
  region: 48.5,0 50.5,0 50.5,8.2 48.5,8.2
  region: 35.85,0 37.85,0 37.85,8.2 35.85,8.2
Bottom Solder:
  region: 48.5,0 50.5,0 50.5,8.2 48.5,8.2
  region: 35.85,0 37.85,0 37.85,8.2 35.85,8.2
Mechanical 1:
  the board outline again, w0.15
Top Component Outline:
  lines w0.1: 22,0.1 22,8.1 ; 35.85,0 35.85,8.2 ; 36.85,0 36.85,8.2 ; 37.85,0 37.85,8.2 ; 48.5,0 48.5,8.2 ; 49.5,0 49.5,8.2 ; 50.5,0 50.5,8.2
Mechanical 30 (Mech30):
  drawing of 737 lines, arcs and shapes, not listed
Mechanical 31 (Mech31):
  drawing of 727 lines, arcs and shapes, not listed
Mechanical 32 (Mech32):
  lines w0.013: 53.759,4 53.769,4.054 ; 53.759,4 53.769,4.054 ; 53.759,4 53.769,4.054 ; 53.759,4 53.769,3.946 ; 53.759,4 53.769,3.946 ; 53.759,4 53.769,3.946 ; 53.769,3.946 53.8,3.9 ; 53.769,3.946 53.8,3.9 ; 53.769,3.946 53.8,3.9 ; 53.769,4.054 53.8,4.1 ; 53.769,4.054 53.8,4.1 ; 53.769,4.054 53.8,4.1 ; 53.8,3.9 53.846,3.869 ; 53.8,3.9 53.846,3.869 ; 53.8,3.9 53.846,3.869 ; 53.8,4.1 53.846,4.131 ; 53.8,4.1 53.846,4.131 ; 53.8,4.1 53.846,4.131 ; 53.846,3.869 53.9,3.859 ; 53.846,3.869 53.9,3.859 ; 53.846,3.869 53.9,3.859 ; 53.846,4.131 53.9,4.141 ; 53.846,4.131 53.9,4.141 ; 53.846,4.131 53.9,4.141 ; 53.9,3.859 53.954,3.869 ; 53.9,3.859 53.954,3.869 ; 53.9,3.859 53.954,3.869 ; 53.9,4.141 53.954,4.131 ; 53.9,4.141 53.954,4.131 ; 53.9,4.141 53.954,4.131 ; 53.954,3.869 54,3.9 ; 53.954,3.869 54,3.9 ; 53.954,3.869 54,3.9 ; 53.954,4.131 54,4.1 ; 53.954,4.131 54,4.1 ; 53.954,4.131 54,4.1 ; 54,3.9 54.031,3.946 ; 54,3.9 54.031,3.946 ; 54,3.9 54.031,3.946 ; 54,4.1 54.031,4.054 ; 54,4.1 54.031,4.054 ; 54,4.1 54.031,4.054 ; 54.031,3.946 54.041,4 ; 54.031,3.946 54.041,4 ; 54.031,3.946 54.041,4 ; 54.031,4.054 54.041,4 ; 54.031,4.054 54.041,4 ; 54.031,4.054 54.041,4

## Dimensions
22,-0.204 to 36.85,-0.204 on Mechanical 10
0,-0.229 to 0,8.2 on Mechanical 10
50.6,8.25 to 48.6,8.25 on Mechanical 10
64,0 to 49.5,-0.204 on Mechanical 10
36.85,0 to 49.5,0 on Mechanical 10
0,0 to 22,0.6 on Mechanical 10
0,0 to 0,8.2 on Mechanical 10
